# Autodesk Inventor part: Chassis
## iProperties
Author: Standard
Created: 2002-11
Part Number: Chassis
Material: Standard
Document SubType Name: Modellieren
Designer: Standard
Control State: 0
Master: False
Checked Out: False
PropertySet Name: Design Tracking Control
Shininess: 20.0
Angle Display Precision: 2
Document Length Units: 11269
Document Angle Units: 11283
Document Time Units: 11279
Document Mass Units: 11290
Document Length Units Precision: 3
Document Angle Units Precision: 2
Compacted: False
PropertySet Name: _Private Model Information
Density: 0.0
Volumn: 0.0
Area: 0.0
PropertySet Name: Model Information
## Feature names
1. Extrusion1
